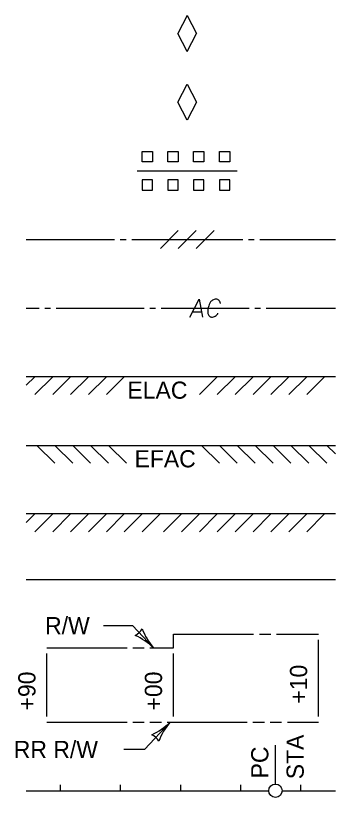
# Model space of a CAD drawing. Extents: x 49991.4 to 50021, y 49987.6 to 50011.4.
# Drawn here: x 50003.934 to 50005.051, y 49993.484 to 49996.218 of the extents above; entities that cross this region are included whole.
import ezdxf

# ---------------------------------------------------------------- set-up
doc = ezdxf.new("R2010")
doc.units = 0
for name, color, linetype in [('Level 1', 7, 'Continuous'), ('Level 2', 7, 'Continuous'), ('Level 3', 7, 'Continuous')]:
    doc.layers.add(name, color=color, linetype=linetype)

msp = doc.modelspace()

# ---------------------------------------------------------------- linework, layer by layer
at = {"layer": 'Level 1'}
for p, q in [((50004.5331, 49996.2181), (50004.5001, 49996.1552)), ((50004.5331, 49996.2181), (50004.5661, 49996.1552)), ((50004.5331, 49996.0923), (50004.5001, 49996.1552)), ((50004.5331, 49996.0923), (50004.5661, 49996.1552)), ((50004.5001, 49995.9152), (50004.5331, 49995.9781)), ((50004.5331, 49995.9781), (50004.5661, 49995.9152)), ((50004.5331, 49995.8523), (50004.5001, 49995.9152)), ((50004.5661, 49995.9152), (50004.5331, 49995.8523)), ((50004.3758, 49995.7425), (50004.4118, 49995.7425)), ((50004.3758, 49995.7065), (50004.3758, 49995.7425)), ((50004.4118, 49995.7425), (50004.4118, 49995.7065)), ((50004.4658, 49995.7425), (50004.5018, 49995.7425)), ((50004.4658, 49995.7065), (50004.4658, 49995.7425)), ((50004.5018, 49995.7425), (50004.5018, 49995.7065)), ((50004.5558, 49995.7425), (50004.5918, 49995.7425)), ((50004.5558, 49995.7065), (50004.5558, 49995.7425)), ((50004.5918, 49995.7425), (50004.5918, 49995.7065)), ((50004.6458, 49995.7425), (50004.6818, 49995.7425)), ((50004.6458, 49995.7065), (50004.6458, 49995.7425)), ((50004.6818, 49995.7425), (50004.6818, 49995.7065)), ((50004.4118, 49995.7065), (50004.3758, 49995.7065)), ((50004.5018, 49995.7065), (50004.4658, 49995.7065)), ((50004.5918, 49995.7065), (50004.5558, 49995.7065)), ((50004.6818, 49995.7065), (50004.6458, 49995.7065)), ((50004.3582, 49995.6753), (50004.7079, 49995.6753)), ((50004.4118, 49995.6442), (50004.3758, 49995.6442)), ((50004.3758, 49995.6442), (50004.3758, 49995.6082)), ((50004.4118, 49995.6082), (50004.4118, 49995.6442)), ((50004.5018, 49995.6442), (50004.4658, 49995.6442)), ((50004.4658, 49995.6442), (50004.4658, 49995.6082)), ((50004.5018, 49995.6082), (50004.5018, 49995.6442)), ((50004.5918, 49995.6442), (50004.5558, 49995.6442)), ((50004.5558, 49995.6442), (50004.5558, 49995.6082)), ((50004.5918, 49995.6082), (50004.5918, 49995.6442)), ((50004.6818, 49995.6442), (50004.6458, 49995.6442)), ((50004.6458, 49995.6442), (50004.6458, 49995.6082)), ((50004.6818, 49995.6082), (50004.6818, 49995.6442)), ((50004.3758, 49995.6082), (50004.4118, 49995.6082)), ((50004.4658, 49995.6082), (50004.5018, 49995.6082)), ((50004.5558, 49995.6082), (50004.5918, 49995.6082)), ((50004.6458, 49995.6082), (50004.6818, 49995.6082)), ((50004.4396, 49995.404), (50004.5021, 49995.4665)), ((50004.5021, 49995.404), (50004.5646, 49995.4665)), ((50004.5646, 49995.404), (50004.6271, 49995.4665)), ((50003.9708, 49995.4352), (50004.2795, 49995.4352)), ((50004.2996, 49995.4352), (50004.3196, 49995.4352)), ((50004.3396, 49995.4352), (50004.7271, 49995.4352)), ((50004.7471, 49995.4352), (50004.7671, 49995.4352)), ((50004.7871, 49995.4352), (50005.0508, 49995.4352)), ((50004.6084, 49995.2029), (50004.6074, 49995.1994)), ((50004.6098, 49995.2073), (50004.6084, 49995.2029)), ((50004.6123, 49995.2122), (50004.6098, 49995.2073)), ((50004.6138, 49995.2147), (50004.6123, 49995.2122)), ((50004.6152, 49995.2171), (50004.6138, 49995.2147)), ((50004.6167, 49995.2191), (50004.6152, 49995.2171)), ((50004.6192, 49995.2211), (50004.6167, 49995.2191)), ((50004.6216, 49995.2226), (50004.6192, 49995.2211)), ((50004.6246, 49995.224), (50004.6216, 49995.2226)), ((50004.6271, 49995.225), (50004.6246, 49995.224)), ((50004.6305, 49995.226), (50004.6271, 49995.225)), ((50004.6334, 49995.2265), (50004.6305, 49995.226)), ((50004.6344, 49995.2265), (50004.6334, 49995.2265)), ((50004.6369, 49995.226), (50004.6344, 49995.2265)), ((50004.6398, 49995.225), (50004.6369, 49995.226)), ((50004.6418, 49995.224), (50004.6398, 49995.225)), ((50004.6438, 49995.2226), (50004.6418, 49995.224)), ((50004.6453, 49995.2211), (50004.6438, 49995.2226)), ((50004.6467, 49995.2191), (50004.6453, 49995.2211)), ((50004.6472, 49995.2181), (50004.6467, 49995.2191)), ((50004.6482, 49995.2162), (50004.6472, 49995.2181)), ((50004.6487, 49995.2142), (50004.6482, 49995.2162)), ((50004.6492, 49995.2122), (50004.6487, 49995.2142)), ((50004.6492, 49995.2108), (50004.6492, 49995.2122)), ((50003.9708, 49995.1952), (50004.0156, 49995.1952)), ((50004.0356, 49995.1952), (50004.0556, 49995.1952)), ((50004.0756, 49995.1952), (50004.3824, 49995.1952)), ((50004.4024, 49995.1952), (50004.4224, 49995.1952)), ((50004.4424, 49995.1952), (50004.5708, 49995.1952)), ((50004.5522, 49995.1827), (50004.5833, 49995.1827)), ((50004.5708, 49995.1952), (50004.6208, 49995.1952)), ((50004.6054, 49995.1896), (50004.6049, 49995.1857)), ((50004.6049, 49995.1857), (50004.6049, 49995.1812)), ((50004.6049, 49995.1812), (50004.6054, 49995.1763)), ((50004.6064, 49995.195), (50004.6054, 49995.1896)), ((50004.6054, 49995.1763), (50004.6064, 49995.1738)), ((50004.6069, 49995.1975), (50004.6064, 49995.195)), ((50004.6064, 49995.1738), (50004.6079, 49995.1714)), ((50004.6074, 49995.1994), (50004.6069, 49995.1975)), ((50004.6208, 49995.1952), (50004.7492, 49995.1952)), ((50004.6374, 49995.1724), (50004.6398, 49995.1753)), ((50004.6398, 49995.1753), (50004.6408, 49995.1773)), ((50004.7692, 49995.1952), (50004.7892, 49995.1952)), ((50004.8092, 49995.1952), (50005.0508, 49995.1952)), ((50004.6079, 49995.1714), (50004.6088, 49995.1699)), ((50004.6088, 49995.1699), (50004.6108, 49995.1674)), ((50004.6108, 49995.1674), (50004.6138, 49995.165)), ((50004.6138, 49995.165), (50004.6157, 49995.1645)), ((50004.6157, 49995.1645), (50004.6187, 49995.164)), ((50004.6187, 49995.164), (50004.6207, 49995.164)), ((50004.6207, 49995.164), (50004.6211, 49995.164)), ((50004.6211, 49995.164), (50004.6246, 49995.1645)), ((50004.6246, 49995.1645), (50004.6285, 49995.1655)), ((50004.6285, 49995.1655), (50004.631, 49995.167)), ((50004.631, 49995.167), (50004.6344, 49995.1694)), ((50004.6344, 49995.1694), (50004.6374, 49995.1724)), ((50004.0008, 49994.9552), (50003.9708, 49994.9252)), ((50004.4758, 49994.9552), (50003.9708, 49994.9552)), ((50004.0633, 49994.9552), (50004.0008, 49994.8927)), ((50004.1258, 49994.9552), (50004.0633, 49994.8927)), ((50004.1883, 49994.9552), (50004.1258, 49994.8927)), ((50004.2508, 49994.9552), (50004.1883, 49994.8927)), ((50004.3133, 49994.9552), (50004.2508, 49994.8927)), ((50005.0508, 49994.9552), (50004.4758, 49994.9552)), ((50004.6383, 49994.9552), (50004.5758, 49994.8927)), ((50004.7008, 49994.9552), (50004.6383, 49994.8927)), ((50004.7633, 49994.9552), (50004.7008, 49994.8927)), ((50004.8258, 49994.9552), (50004.7633, 49994.8927)), ((50004.8883, 49994.9552), (50004.8258, 49994.8927)), ((50004.9508, 49994.9552), (50004.8883, 49994.8927)), ((50005.0133, 49994.9552), (50004.9508, 49994.8927)), ((50003.9708, 49994.7152), (50004.5458, 49994.7152)), ((50004.0083, 49994.7152), (50004.0708, 49994.6527)), ((50004.0708, 49994.7152), (50004.1333, 49994.6527)), ((50004.1333, 49994.7152), (50004.1958, 49994.6527)), ((50004.1958, 49994.7152), (50004.2583, 49994.6527)), ((50004.2583, 49994.7152), (50004.3208, 49994.6527)), ((50004.5458, 49994.7152), (50005.0508, 49994.7152)), ((50004.5833, 49994.7152), (50004.6458, 49994.6527)), ((50004.6458, 49994.7152), (50004.7083, 49994.6527)), ((50004.7083, 49994.7152), (50004.7708, 49994.6527)), ((50004.7708, 49994.7152), (50004.8333, 49994.6527)), ((50004.8333, 49994.7152), (50004.8958, 49994.6527)), ((50004.8958, 49994.7152), (50004.9583, 49994.6527)), ((50004.9583, 49994.7152), (50005.0208, 49994.6527)), ((50005.0208, 49994.7152), (50005.0508, 49994.6852)), ((50004.0008, 49994.4752), (50003.9708, 49994.4452)), ((50004.4758, 49994.4752), (50003.9708, 49994.4752)), ((50004.0633, 49994.4752), (50004.0008, 49994.4127)), ((50004.1258, 49994.4752), (50004.0633, 49994.4127)), ((50004.1883, 49994.4752), (50004.1258, 49994.4127)), ((50004.2508, 49994.4752), (50004.1883, 49994.4127)), ((50004.3133, 49994.4752), (50004.2508, 49994.4127)), ((50004.3758, 49994.4752), (50004.3133, 49994.4127)), ((50004.4383, 49994.4752), (50004.3758, 49994.4127)), ((50004.5133, 49994.4752), (50004.4508, 49994.4127)), ((50005.0508, 49994.4752), (50004.4758, 49994.4752)), ((50004.5758, 49994.4752), (50004.5133, 49994.4127)), ((50004.6383, 49994.4752), (50004.5758, 49994.4127)), ((50004.7008, 49994.4752), (50004.6383, 49994.4127)), ((50004.7633, 49994.4752), (50004.7008, 49994.4127)), ((50004.8258, 49994.4752), (50004.7633, 49994.4127)), ((50004.8883, 49994.4752), (50004.8258, 49994.4127)), ((50004.9508, 49994.4752), (50004.8883, 49994.4127)), ((50005.0133, 49994.4752), (50004.9508, 49994.4127)), ((50005.0508, 49994.2451), (50003.9708, 49994.2451)), ((50004.4854, 49994.0067), (50004.4854, 49994.0544)), ((50004.4854, 49994.0544), (50004.7654, 49994.0544)), ((50004.7854, 49994.0544), (50004.8254, 49994.0544)), ((50004.8454, 49994.0544), (50004.9922, 49994.0544)), ((50004.9922, 49993.7669), (50004.9922, 49994.0344)), ((50004.0431, 49994.0067), (50004.3231, 49994.0067)), ((50004.3431, 49994.0067), (50004.3831, 49994.0067)), ((50004.4031, 49994.0067), (50004.4854, 49994.0067)), ((50004.0431, 49993.7669), (50004.0431, 49993.9867)), ((50004.4854, 49993.7669), (50004.4854, 49993.9867)), ((50004.0431, 49993.7469), (50004.3231, 49993.7469)), ((50004.3431, 49993.7469), (50004.3831, 49993.7469)), ((50004.4031, 49993.7469), (50004.4431, 49993.7469)), ((50004.4631, 49993.7469), (50004.7431, 49993.7469)), ((50004.7631, 49993.7469), (50004.8031, 49993.7469)), ((50004.8231, 49993.7469), (50004.8631, 49993.7469)), ((50004.8831, 49993.7469), (50004.9922, 49993.7469)), ((50004.8414, 49993.5305), (50004.8414, 49993.6661)), ((50003.9708, 49993.5069), (50004.818, 49993.5069)), ((50004.0908, 49993.5069), (50004.0908, 49993.5272)), ((50004.3008, 49993.5069), (50004.3008, 49993.5272)), ((50004.5108, 49993.5069), (50004.5108, 49993.5272)), ((50004.7208, 49993.5069), (50004.7208, 49993.5272)), ((50004.8647, 49993.5069), (50005.0508, 49993.5069)), ((50004.9308, 49993.5069), (50004.9308, 49993.5272))]:
    msp.add_line(p, q, dxfattribs=at)
msp.add_lwpolyline([(50004.5424, 49995.164), (50004.5754, 49995.2265), (50004.5867, 49995.164)], dxfattribs=at)
msp.add_circle((50004.8414, 49993.5073), 0.0233, dxfattribs=at)
at = {"layer": 'Level 3'}
for p, q in [((50004.2412, 49994.0846), (50004.3423, 49994.0846)), ((50004.416, 49994.0067), (50004.3423, 49994.0846)), ((50004.4736, 49993.7469), (50004.3841, 49993.6515)), ((50004.3841, 49993.6515), (50004.3118, 49993.6515))]:
    msp.add_line(p, q, dxfattribs=at)
for centre, radius, start, end in [((50004.3279, 49994.0998), 0.0548, 295.5498, 331.2721), ((50004.5836, 49994.1527), 0.2223, 200.867, 221.0505), ((50004.2548, 49993.8384), 0.233, 46.2383, 65.4881), ((50004.3179, 49993.9056), 0.2223, 294.2757, 314.4592), ((50004.6512, 49993.5961), 0.233, 139.647, 158.8968), ((50004.3859, 49993.6535), 0.0548, 28.9585, 64.6809)]:
    msp.add_arc(centre, radius, start, end, dxfattribs=at)

# ---------------------------------------------------------------- texts
at = {"layer": 'Level 2'}
for s, p in [('ELAC', (50004.3245, 49994.8782)), ('EFAC', (50004.3492, 49994.6382)), ('R/W', (50004.0368, 49994.0546)), ('RR R/W', (50003.9274, 49993.6215))]:
    msp.add_text(s, height=0.06, dxfattribs=at).set_placement(p)
for s, p in [('+10', (50004.9522, 49993.8117)), ('+90', (50004.0031, 49993.7879)), ('+00', (50004.4454, 49993.7879)), ('STA', (50004.9404, 49993.5473)), ('PC', (50004.8168, 49993.5503))]:
    msp.add_text(s, height=0.06, rotation=90, dxfattribs=at).set_placement(p)

doc.saveas('drawing.dxf')
